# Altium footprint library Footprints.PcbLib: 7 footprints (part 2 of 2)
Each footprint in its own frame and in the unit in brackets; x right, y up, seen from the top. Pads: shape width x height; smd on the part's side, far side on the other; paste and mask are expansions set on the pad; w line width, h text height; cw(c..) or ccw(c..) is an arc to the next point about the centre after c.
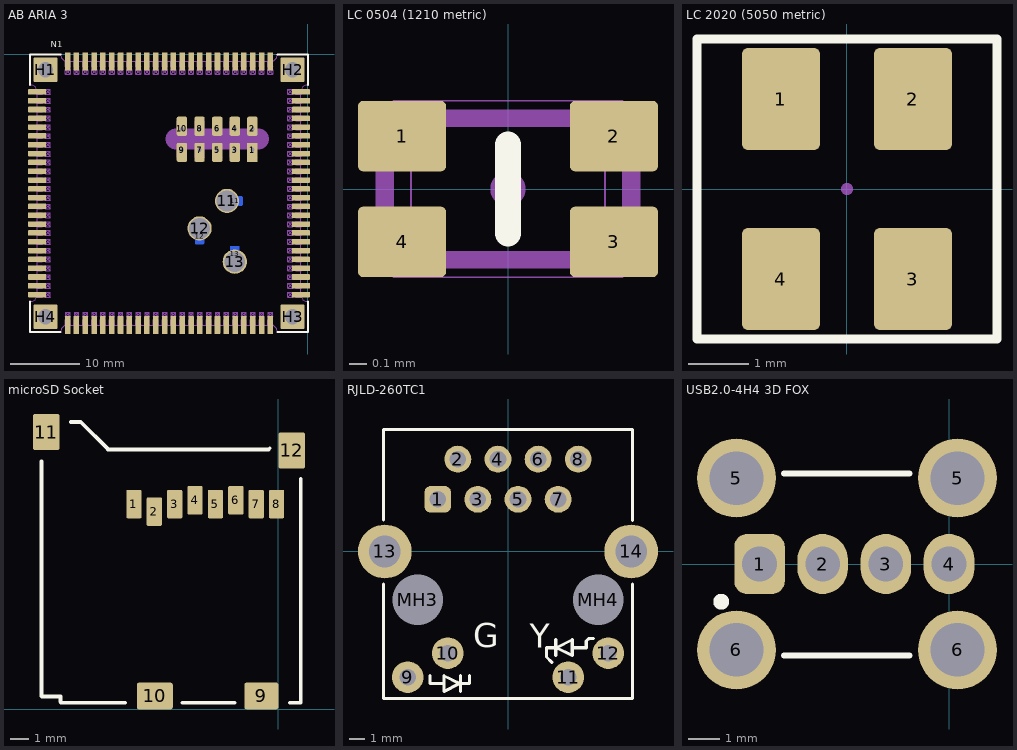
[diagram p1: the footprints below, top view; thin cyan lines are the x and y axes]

## AB ARIA 3 [mm]
height 1.7
pads (126):
  rect 1.5x2.5 hole 0.6 copper offset 0,-0.5 paste-0.1: 1(-7.98,-13.725)
  rect 1.5x2.2 smd paste+0.1: 1(-7.98,-13.83)
  rrect30% 1.5x2.5 hole 0.6 copper offset 0,0.5 paste-0.1: 2(-7.98,-10.725) 4(-10.52,-10.725) 6(-13.06,-10.725) 8(-15.6,-10.725) 10(-18.14,-10.725)
  rrect30% 1.5x2.2 smd paste+0.1: 2(-7.98,-10.62) 3(-10.52,-13.83) 4(-10.52,-10.62) 5(-13.06,-13.83) 6(-13.06,-10.62) 7(-15.6,-13.83) 8(-15.6,-10.62) 9(-18.14,-13.83) 10(-18.14,-10.62)
  rrect30% 1.5x2.5 hole 0.6 copper offset 0,-0.5 paste-0.1: 3(-10.52,-13.725) 5(-13.06,-13.725) 7(-15.6,-13.725) 9(-18.14,-13.725)
  round 3.5 hole 3 paste-1 mask+0.1: 11(-11.644,-21.115) 12(-15.6,-25.07) 13(-10.52,-29.86)
  rrect20% 2.25x1.3 smd far side: 11(-10.52,-21.115)
  rrect20% 1.3x2.25 smd far side: 12(-15.6,-26.195) 13(-10.52,-28.735)
  rrect20% 2.6x0.8 smd paste+0.05: E1(-1,-5.395) E2(-1,-6.665) E3(-1,-7.935) E4(-1,-9.205) E5(-1,-10.475) E6(-1,-11.745) E7(-1,-13.015) E8(-1,-14.285) E9(-1,-15.555) E10(-1,-16.825) E11(-1,-18.095) E12(-1,-19.365) E13(-1,-20.635) E14(-1,-21.905) E15(-1,-23.175) E16(-1,-24.445) E17(-1,-25.715) E18(-1,-26.985) E19(-1,-28.255) E20(-1,-29.525) E21(-1,-30.795) E22(-1,-32.065) E23(-1,-33.335) E24(-1,-34.605) W1(-39,-34.605) W2(-39,-33.335) W3(-39,-32.065) W4(-39,-30.795) W5(-39,-29.525) W6(-39,-28.255) W7(-39,-26.985) W8(-39,-25.715) W9(-39,-24.445) W10(-39,-23.175) W11(-39,-21.905) W12(-39,-20.635) W13(-39,-19.365) W14(-39,-18.095) W15(-39,-16.825) W16(-39,-15.555) W17(-39,-14.285) W18(-39,-13.015) W19(-39,-11.745) W20(-39,-10.475) W21(-39,-9.205) W22(-39,-7.935) W23(-39,-6.665) W24(-39,-5.395)
  rrect10% 3.5x3.5 hole 2.2 mask+0.2: H1(-37.8,-2.2) H2(-2.2,-2.2) H3(-2.2,-37.8) H4(-37.8,-37.8)
  rrect20% 0.8x2.6 smd paste+0.05: N1(-34.605,-1) N2(-33.335,-1) N3(-32.065,-1) N4(-30.795,-1) N5(-29.525,-1) N6(-28.255,-1) N7(-26.985,-1) N8(-25.715,-1) N9(-24.445,-1) N10(-23.175,-1) N11(-21.905,-1) N12(-20.635,-1) N13(-19.365,-1) N14(-18.095,-1) N15(-16.825,-1) N16(-15.555,-1) N17(-14.285,-1) N18(-13.015,-1) N19(-11.745,-1) N20(-10.475,-1) N21(-9.205,-1) N22(-7.935,-1) N23(-6.665,-1) N24(-5.395,-1) S1(-5.395,-39) S2(-6.665,-39) S3(-7.935,-39) S4(-9.205,-39) S5(-10.475,-39) S6(-11.745,-39) S7(-13.015,-39) S8(-14.285,-39) S9(-15.555,-39) S10(-16.825,-39) S11(-18.095,-39) S12(-19.365,-39) S13(-20.635,-39) S14(-21.905,-39) S15(-23.175,-39) S16(-24.445,-39) S17(-25.715,-39) S18(-26.985,-39) S19(-28.255,-39) S20(-29.525,-39) S21(-30.795,-39) S22(-32.065,-39) S23(-33.335,-39) S24(-34.605,-39)
Top Overlay:
  lines w0.3: -40,-35.605 -40,-40 ; -40,-4.395 -40,0 -35.605,0 ; -35.605,-40 -40,-40 ; -4.395,-40 0,-40 0,-35.605 ; -4.395,0 0,0 ; 0,-4.395 0,0 ; -40,-40 -40,-40 ; -35.605,0 -35.605,0 ; 0,0 0,0
  text "N1" at -37.034,0.701 h1.52
Top Paste:
  lines w0.9: -40.752,-7.933 -40.452,-7.933 ; -40.75,-33.335 -40.45,-33.335 ; -40.75,-32.065 -40.45,-32.065 ; -40.75,-30.795 -40.45,-30.795 ; -40.75,-29.525 -40.45,-29.525 ; -40.75,-28.255 -40.45,-28.255 ; -40.75,-26.985 -40.45,-26.985 ; -40.75,-25.715 -40.45,-25.715 ; -40.75,-24.445 -40.45,-24.445 ; -40.75,-23.175 -40.45,-23.175 ; -40.75,-21.905 -40.45,-21.905 ; -40.75,-20.635 -40.45,-20.635 ; -40.75,-19.365 -40.45,-19.365 ; -40.75,-18.095 -40.45,-18.095 ; -40.75,-16.825 -40.45,-16.825 ; -40.75,-15.555 -40.45,-15.555 ; -40.75,-13.015 -40.45,-13.015 ; -40.75,-11.745 -40.45,-11.745 ; -40.75,-10.475 -40.45,-10.475 ; -40.75,-9.205 -40.45,-9.205 ; -40.75,-6.665 -40.45,-6.665 ; -40.75,-5.395 -40.45,-5.395 ; -40.749,-34.604 -40.449,-34.604 ; -34.605,-40.75 -34.605,-40.45 ; -34.605,0.45 -34.605,0.75 ; -33.335,-40.75 -33.335,-40.45 ; -33.335,0.45 -33.335,0.75 ; -32.065,-40.75 -32.065,-40.45 ; -32.065,0.45 -32.065,0.75 ; -30.795,-40.75 -30.795,-40.45 ; -30.795,0.45 -30.795,0.75 ; -29.525,-40.75 -29.525,-40.45 ; -29.525,0.45 -29.525,0.75 ; -28.255,-40.75 -28.255,-40.45 ; -28.255,0.45 -28.255,0.75 ; -26.985,-40.75 -26.985,-40.45 ; -26.985,0.45 -26.985,0.75 ; -25.715,-40.75 -25.715,-40.45 ; -25.715,0.45 -25.715,0.75 ; -24.445,-40.75 -24.445,-40.45 ; -24.445,0.45 -24.445,0.75 ; -23.175,-40.75 -23.175,-40.45 ; -23.175,0.45 -23.175,0.75 ; -21.905,-40.75 -21.905,-40.45 ; -21.905,0.45 -21.905,0.75 ; -20.635,-40.75 -20.635,-40.45 ; -20.635,0.45 -20.635,0.75 ; -19.365,-40.75 -19.365,-40.45 ; -19.365,0.45 -19.365,0.75 ; -18.095,-40.75 -18.095,-40.45 ; -18.095,0.45 -18.095,0.75 ; -16.825,-40.75 -16.825,-40.45 ; -16.825,0.45 -16.825,0.75 ; -15.555,-40.75 -15.555,-40.45 ; -15.555,0.45 -15.555,0.75 ; -14.285,-40.75 -14.285,-40.45 ; -14.285,0.45 -14.285,0.75 ; -13.015,-40.75 -13.015,-40.45 ; -13.015,0.45 -13.015,0.75 ; -11.745,-40.75 -11.745,-40.45 ; -11.745,0.45 -11.745,0.75 ; -10.475,-40.75 -10.475,-40.45 ; -10.475,0.45 -10.475,0.75 ; -9.205,-40.75 -9.205,-40.45 ; -9.205,0.45 -9.205,0.75 ; -7.935,-40.75 -7.935,-40.45 ; -7.935,0.45 -7.935,0.75 ; -6.665,-40.75 -6.665,-40.45 ; -6.665,0.45 -6.665,0.75 ; -5.395,-40.75 -5.395,-40.45 ; -5.395,0.45 -5.395,0.75 ; 0.45,-34.605 0.75,-34.605 ; 0.45,-33.335 0.75,-33.335 ; 0.45,-32.065 0.75,-32.065 ; 0.45,-30.795 0.75,-30.795 ; 0.45,-29.525 0.75,-29.525 ; 0.45,-28.255 0.75,-28.255 ; 0.45,-26.985 0.75,-26.985 ; 0.45,-25.715 0.75,-25.715 ; 0.45,-24.445 0.75,-24.445 ; 0.45,-23.175 0.75,-23.175 ; 0.45,-21.905 0.75,-21.905 ; 0.45,-20.635 0.75,-20.635 ; 0.45,-19.365 0.75,-19.365 ; 0.45,-18.095 0.75,-18.095 ; 0.45,-16.825 0.75,-16.825 ; 0.45,-15.555 0.75,-15.555 ; 0.45,-14.285 0.75,-14.285 ; 0.45,-13.015 0.75,-13.015 ; 0.45,-11.745 0.75,-11.745 ; 0.45,-10.475 0.75,-10.475 ; 0.45,-9.205 0.75,-9.205 ; 0.45,-7.935 0.75,-7.935 ; 0.45,-6.665 0.75,-6.665 ; 0.45,-5.395 0.75,-5.395 ; -40.75,-14.285 -40.45,-14.285 -40.75,-14.285
Mechanical 1:
  lines w0.1: -5.395,-39 cw(c-5.395,-40) -4.395,-40 0,-40 0,-35.605 cw(c0,-34.605) -1,-34.605 -1,-5.395 cw(c0,-5.395) 0,-4.395 0,0 -4.395,0 cw(c-5.395,0) -5.395,-1 -34.605,-1 cw(c-34.605,0) -35.605,0 -40,0 -40,-4.395 cw(c-40,-5.395) -39,-5.395 -39,-34.605 cw(c-40,-34.605) -40,-35.605 -40,-40 -35.605,-40 cw(c-34.605,-40) -34.605,-39 -5.345,-39
Mechanical 6:
  lines w3: -19,-12.2 -7.12,-12.2
Mechanical 15:
  drawing of 1308 lines, arcs and shapes, not listed
3D body: height 0.02, standoff -0.03, extent -11.214,-29.433 -9.82,-28.036
3D body: height 0.02, standoff -0.03, extent -16.294,-26.893 -14.9,-25.496
3D body: height 0.1, standoff 0.01, extent -18.79,-14.83 -17.49,-12.83
3D body: height 0.1, standoff 0.01, extent -16.25,-14.83 -14.95,-12.83
3D body: height 0.1, standoff 0.01, extent -13.71,-14.83 -12.41,-12.83
3D body: height 0.1, standoff 0.01, extent -11.17,-14.83 -9.87,-12.83
3D body: height 0.1, standoff 0.01, extent -8.63,-14.83 -7.33,-12.83
3D body: height 0.1, standoff 0.01, extent -18.79,-11.62 -17.49,-9.62
3D body: height 0.1, standoff 0.01, extent -16.25,-11.62 -14.95,-9.62
3D body: height 0.1, standoff 0.01, extent -13.71,-11.62 -12.41,-9.62
3D body: height 0.1, standoff 0.01, extent -11.17,-11.62 -9.87,-9.62
3D body: height 0.1, standoff 0.01, extent -8.63,-11.62 -7.33,-9.62
3D body: height 1.51, standoff 0.01, extent -20.64,-6.3 -19.28,-4.73
3D body: height 1.51, standoff 0.01, extent -21.599,-4.001 -18.4,-2.4
3D body: height 1.51, standoff 1.4, extent -2.18,-5.745 -0.95,-5.045
3D body: height 0.1, standoff 0.01, extent -2.88,-5.745 -2.18,-5.045
3D body: height 1.4, standoff 0.01, extent -1.77,-5.745 -0.95,-5.045
3D body: height 1.4, standoff 0.01, extent -1.77,-7.015 -0.95,-6.315
3D body: height 0.1, standoff 0.01, extent -2.88,-7.015 -2.18,-6.315
3D body: height 1.51, standoff 1.4, extent -1.77,-7.015 -0.95,-6.315
3D body: height 1.4, standoff 0.01, extent -1.77,-8.285 -0.95,-7.585
3D body: height 0.1, standoff 0.01, extent -2.88,-8.285 -2.18,-7.585
3D body: height 1.51, standoff 1.4, extent -1.77,-8.285 -0.95,-7.585
3D body: height 1.4, standoff 0.01, extent -1.77,-9.555 -0.95,-8.855
3D body: height 0.1, standoff 0.01, extent -2.88,-9.555 -2.18,-8.855
3D body: height 1.51, standoff 1.4, extent -1.77,-9.555 -0.95,-8.855
3D body: height 1.4, standoff 0.01, extent -1.77,-10.825 -0.95,-10.125
3D body: height 0.1, standoff 0.01, extent -2.88,-10.825 -2.18,-10.125
3D body: height 1.51, standoff 1.4, extent -1.77,-10.825 -0.95,-10.125
3D body: height 1.4, standoff 0.01, extent -1.77,-12.095 -0.95,-11.395
3D body: height 0.1, standoff 0.01, extent -2.88,-12.095 -2.18,-11.395
3D body: height 1.51, standoff 1.4, extent -1.77,-12.095 -0.95,-11.395
3D body: height 1.4, standoff 0.01, extent -1.77,-13.365 -0.95,-12.665
3D body: height 0.1, standoff 0.01, extent -2.88,-13.365 -2.18,-12.665
3D body: height 1.51, standoff 1.4, extent -1.77,-13.365 -0.95,-12.665
3D body: height 1.4, standoff 0.01, extent -1.77,-14.635 -0.95,-13.935
3D body: height 0.1, standoff 0.01, extent -2.88,-14.635 -2.18,-13.935
3D body: height 1.51, standoff 1.4, extent -1.77,-14.635 -0.95,-13.935
3D body: height 1.4, standoff 0.01, extent -1.77,-15.905 -0.95,-15.205
3D body: height 0.1, standoff 0.01, extent -2.88,-15.905 -2.18,-15.205
3D body: height 1.51, standoff 1.4, extent -1.77,-15.905 -0.95,-15.205
3D body: height 1.4, standoff 0.01, extent -1.77,-17.175 -0.95,-16.475
3D body: height 0.1, standoff 0.01, extent -2.88,-17.175 -2.18,-16.475
3D body: height 1.51, standoff 1.4, extent -1.77,-17.175 -0.95,-16.475
3D body: height 1.4, standoff 0.01, extent -1.77,-18.445 -0.95,-17.745
3D body: height 0.1, standoff 0.01, extent -2.88,-18.445 -2.18,-17.745
3D body: height 1.51, standoff 1.4, extent -1.77,-18.445 -0.95,-17.745
3D body: height 1.4, standoff 0.01, extent -1.77,-19.715 -0.95,-19.015
3D body: height 0.1, standoff 0.01, extent -2.88,-19.715 -2.18,-19.015
3D body: height 1.51, standoff 1.4, extent -1.77,-19.715 -0.95,-19.015
3D body: height 1.4, standoff 0.01, extent -1.77,-20.985 -0.95,-20.285
3D body: height 0.1, standoff 0.01, extent -2.88,-20.985 -2.18,-20.285
3D body: height 1.51, standoff 1.4, extent -1.77,-20.985 -0.95,-20.285
3D body: height 1.4, standoff 0.01, extent -1.77,-22.255 -0.95,-21.555
3D body: height 0.1, standoff 0.01, extent -2.88,-22.255 -2.18,-21.555
3D body: height 1.51, standoff 1.4, extent -1.77,-22.255 -0.95,-21.555
3D body: height 1.4, standoff 0.01, extent -1.77,-23.525 -0.95,-22.825
3D body: height 0.1, standoff 0.01, extent -2.88,-23.525 -2.18,-22.825
3D body: height 1.51, standoff 1.4, extent -1.77,-23.525 -0.95,-22.825
3D body: height 1.4, standoff 0.01, extent -1.77,-24.795 -0.95,-24.095
3D body: height 0.1, standoff 0.01, extent -2.88,-24.795 -2.18,-24.095
3D body: height 1.51, standoff 1.4, extent -1.77,-24.795 -0.95,-24.095
3D body: height 1.4, standoff 0.01, extent -1.77,-26.065 -0.95,-25.365
3D body: height 0.1, standoff 0.01, extent -2.88,-26.065 -2.18,-25.365
3D body: height 1.51, standoff 1.4, extent -1.77,-26.065 -0.95,-25.365
3D body: height 1.4, standoff 0.01, extent -1.77,-27.335 -0.95,-26.635
3D body: height 0.1, standoff 0.01, extent -2.88,-27.335 -2.18,-26.635
3D body: height 1.51, standoff 1.4, extent -1.77,-27.335 -0.95,-26.635
3D body: height 1.4, standoff 0.01, extent -1.77,-28.605 -0.95,-27.905
3D body: height 0.1, standoff 0.01, extent -2.88,-28.605 -2.18,-27.905
3D body: height 1.51, standoff 1.4, extent -1.77,-28.605 -0.95,-27.905
3D body: height 1.4, standoff 0.01, extent -1.77,-29.875 -0.95,-29.175
3D body: height 0.1, standoff 0.01, extent -2.88,-29.875 -2.18,-29.175
3D body: height 1.51, standoff 1.4, extent -1.77,-29.875 -0.95,-29.175
3D body: height 1.4, standoff 0.01, extent -1.77,-31.145 -0.95,-30.445
3D body: height 0.1, standoff 0.01, extent -2.88,-31.145 -2.18,-30.445
3D body: height 1.51, standoff 1.4, extent -1.77,-31.145 -0.95,-30.445
3D body: height 1.4, standoff 0.01, extent -1.77,-32.415 -0.95,-31.715
3D body: height 0.1, standoff 0.01, extent -2.88,-32.415 -2.18,-31.715
3D body: height 1.51, standoff 1.4, extent -1.77,-32.415 -0.95,-31.715
3D body: height 1.4, standoff 0.01, extent -1.77,-33.685 -0.95,-32.985
3D body: height 0.1, standoff 0.01, extent -2.88,-33.685 -2.18,-32.985
3D body: height 1.51, standoff 1.4, extent -1.77,-33.685 -0.95,-32.985
3D body: height 1.4, standoff 0.01, extent -1.77,-34.955 -0.95,-34.255
3D body: height 0.1, standoff 0.01, extent -2.88,-34.955 -2.18,-34.255
3D body: height 1.51, standoff 1.4, extent -1.77,-34.955 -0.95,-34.255
3D body: height 1.4, standoff 0.01, extent -5.745,-39.05 -5.045,-38.23
3D body: height 0.1, standoff 0.01, extent -5.745,-37.82 -5.045,-37.12
3D body: height 1.51, standoff 1.4, extent -5.745,-39.05 -5.045,-37.82
3D body: height 1.4, standoff 0.01, extent -7.015,-39.05 -6.315,-38.23
3D body: height 0.1, standoff 0.01, extent -7.015,-37.82 -6.315,-37.12
3D body: height 1.51, standoff 1.4, extent -7.015,-39.05 -6.315,-38.23
3D body: height 1.4, standoff 0.01, extent -8.285,-39.05 -7.585,-38.23
3D body: height 0.1, standoff 0.01, extent -8.285,-37.82 -7.585,-37.12
3D body: height 1.51, standoff 1.4, extent -8.285,-39.05 -7.585,-38.23
3D body: height 1.4, standoff 0.01, extent -9.555,-39.05 -8.855,-38.23
3D body: height 0.1, standoff 0.01, extent -9.555,-37.82 -8.855,-37.12
3D body: height 1.51, standoff 1.4, extent -9.555,-39.05 -8.855,-38.23
3D body: height 1.4, standoff 0.01, extent -10.825,-39.05 -10.125,-38.23
3D body: height 0.1, standoff 0.01, extent -10.825,-37.82 -10.125,-37.12
3D body: height 1.51, standoff 1.4, extent -10.825,-39.05 -10.125,-38.23
3D body: height 1.4, standoff 0.01, extent -12.095,-39.05 -11.395,-38.23
3D body: height 0.1, standoff 0.01, extent -12.095,-37.82 -11.395,-37.12
3D body: height 1.51, standoff 1.4, extent -12.095,-39.05 -11.395,-38.23
3D body: height 1.4, standoff 0.01, extent -13.365,-39.05 -12.665,-38.23
3D body: height 0.1, standoff 0.01, extent -13.365,-37.82 -12.665,-37.12
3D body: height 1.51, standoff 1.4, extent -13.365,-39.05 -12.665,-38.23
3D body: height 1.4, standoff 0.01, extent -14.635,-39.05 -13.935,-38.23
3D body: height 0.1, standoff 0.01, extent -14.635,-37.82 -13.935,-37.12
3D body: height 1.51, standoff 1.4, extent -14.635,-39.05 -13.935,-38.23
3D body: height 1.4, standoff 0.01, extent -15.905,-39.05 -15.205,-38.23
3D body: height 0.1, standoff 0.01, extent -15.905,-37.82 -15.205,-37.12
3D body: height 1.51, standoff 1.4, extent -15.905,-39.05 -15.205,-38.23
3D body: height 1.4, standoff 0.01, extent -17.175,-39.05 -16.475,-38.23
3D body: height 0.1, standoff 0.01, extent -17.175,-37.82 -16.475,-37.12
3D body: height 1.51, standoff 1.4, extent -17.175,-39.05 -16.475,-38.23
3D body: height 1.4, standoff 0.01, extent -18.445,-39.05 -17.745,-38.23
3D body: height 0.1, standoff 0.01, extent -18.445,-37.82 -17.745,-37.12
3D body: height 1.51, standoff 1.4, extent -18.445,-39.05 -17.745,-38.23
3D body: height 1.4, standoff 0.01, extent -19.715,-39.05 -19.015,-38.23
3D body: height 0.1, standoff 0.01, extent -19.715,-37.82 -19.015,-37.12
3D body: height 1.51, standoff 1.4, extent -19.715,-39.05 -19.015,-38.23
3D body: height 1.4, standoff 0.01, extent -20.985,-39.05 -20.285,-38.23
3D body: height 0.1, standoff 0.01, extent -20.985,-37.82 -20.285,-37.12
3D body: height 1.51, standoff 1.4, extent -20.985,-39.05 -20.285,-38.23
3D body: height 1.4, standoff 0.01, extent -22.255,-39.05 -21.555,-38.23
3D body: height 0.1, standoff 0.01, extent -22.255,-37.82 -21.555,-37.12
3D body: height 1.51, standoff 1.4, extent -22.255,-39.05 -21.555,-38.23
3D body: height 1.4, standoff 0.01, extent -23.525,-39.05 -22.825,-38.23
3D body: height 0.1, standoff 0.01, extent -23.525,-37.82 -22.825,-37.12
3D body: height 1.51, standoff 1.4, extent -23.525,-39.05 -22.825,-38.23
3D body: height 1.4, standoff 0.01, extent -24.795,-39.05 -24.095,-38.23
3D body: height 0.1, standoff 0.01, extent -24.795,-37.82 -24.095,-37.12
3D body: height 1.51, standoff 1.4, extent -24.795,-39.05 -24.095,-38.23
3D body: height 1.4, standoff 0.01, extent -26.065,-39.05 -25.365,-38.23
3D body: height 0.1, standoff 0.01, extent -26.065,-37.82 -25.365,-37.12
3D body: height 1.51, standoff 1.4, extent -26.065,-39.05 -25.365,-38.23
3D body: height 1.4, standoff 0.01, extent -27.335,-39.05 -26.635,-38.23
3D body: height 0.1, standoff 0.01, extent -27.335,-37.82 -26.635,-37.12
3D body: height 1.51, standoff 1.4, extent -27.335,-39.05 -26.635,-38.23
3D body: height 1.4, standoff 0.01, extent -28.605,-39.05 -27.905,-38.23
3D body: height 0.1, standoff 0.01, extent -28.605,-37.82 -27.905,-37.12
3D body: height 1.51, standoff 1.4, extent -28.605,-39.05 -27.905,-38.23
3D body: height 1.4, standoff 0.01, extent -29.875,-39.05 -29.175,-38.23
3D body: height 0.1, standoff 0.01, extent -29.875,-37.82 -29.175,-37.12
3D body: height 1.51, standoff 1.4, extent -29.875,-39.05 -29.175,-38.23
3D body: height 1.4, standoff 0.01, extent -31.145,-39.05 -30.445,-38.23
3D body: height 0.1, standoff 0.01, extent -31.145,-37.82 -30.445,-37.12
3D body: height 1.51, standoff 1.4, extent -31.145,-39.05 -30.445,-38.23
3D body: height 1.4, standoff 0.01, extent -32.415,-39.05 -31.715,-38.23
3D body: height 0.1, standoff 0.01, extent -32.415,-37.82 -31.715,-37.12
3D body: height 1.51, standoff 1.4, extent -32.415,-39.05 -31.715,-38.23
3D body: height 1.4, standoff 0.01, extent -33.685,-39.05 -32.985,-38.23
3D body: height 0.1, standoff 0.01, extent -33.685,-37.82 -32.985,-37.12
3D body: height 1.51, standoff 1.4, extent -33.685,-39.05 -32.985,-38.23
3D body: height 1.4, standoff 0.01, extent -34.955,-39.05 -34.255,-38.23
3D body: height 0.1, standoff 0.01, extent -34.955,-37.82 -34.255,-37.12
3D body: height 1.51, standoff 1.4, extent -34.955,-39.05 -34.255,-38.23
3D body: height 1.4, standoff 0.01, extent -39.05,-34.955 -38.23,-34.255
3D body: height 0.1, standoff 0.01, extent -37.82,-34.955 -37.12,-34.255
3D body: height 1.51, standoff 1.4, extent -39.05,-34.955 -37.82,-34.255
3D body: height 1.4, standoff 0.01, extent -39.05,-33.685 -38.23,-32.985
3D body: height 0.1, standoff 0.01, extent -37.82,-33.685 -37.12,-32.985
3D body: height 1.51, standoff 1.4, extent -39.05,-33.685 -38.23,-32.985
3D body: height 1.4, standoff 0.01, extent -39.05,-32.415 -38.23,-31.715
3D body: height 0.1, standoff 0.01, extent -37.82,-32.415 -37.12,-31.715
3D body: height 1.51, standoff 1.4, extent -39.05,-32.415 -38.23,-31.715
3D body: height 1.4, standoff 0.01, extent -39.05,-31.145 -38.23,-30.445
3D body: height 0.1, standoff 0.01, extent -37.82,-31.145 -37.12,-30.445
3D body: height 1.51, standoff 1.4, extent -39.05,-31.145 -38.23,-30.445
3D body: height 1.4, standoff 0.01, extent -39.05,-29.875 -38.23,-29.175
3D body: height 0.1, standoff 0.01, extent -37.82,-29.875 -37.12,-29.175
3D body: height 1.51, standoff 1.4, extent -39.05,-29.875 -38.23,-29.175
3D body: height 1.4, standoff 0.01, extent -39.05,-28.605 -38.23,-27.905
3D body: height 0.1, standoff 0.01, extent -37.82,-28.605 -37.12,-27.905
3D body: height 1.51, standoff 1.4, extent -39.05,-28.605 -38.23,-27.905
3D body: height 1.4, standoff 0.01, extent -39.05,-27.335 -38.23,-26.635
3D body: height 0.1, standoff 0.01, extent -37.82,-27.335 -37.12,-26.635
3D body: height 1.51, standoff 1.4, extent -39.05,-27.335 -38.23,-26.635
3D body: height 1.4, standoff 0.01, extent -39.05,-26.065 -38.23,-25.365
3D body: height 0.1, standoff 0.01, extent -37.82,-26.065 -37.12,-25.365
3D body: height 1.51, standoff 1.4, extent -39.05,-26.065 -38.23,-25.365
3D body: height 1.4, standoff 0.01, extent -39.05,-24.795 -38.23,-24.095
3D body: height 0.1, standoff 0.01, extent -37.82,-24.795 -37.12,-24.095
3D body: height 1.51, standoff 1.4, extent -39.05,-24.795 -38.23,-24.095
3D body: height 1.4, standoff 0.01, extent -39.05,-23.525 -38.23,-22.825
3D body: height 0.1, standoff 0.01, extent -37.82,-23.525 -37.12,-22.825
3D body: height 1.51, standoff 1.4, extent -39.05,-23.525 -38.23,-22.825
3D body: height 1.4, standoff 0.01, extent -39.05,-22.255 -38.23,-21.555
3D body: height 0.1, standoff 0.01, extent -37.82,-22.255 -37.12,-21.555
3D body: height 1.51, standoff 1.4, extent -39.05,-22.255 -38.23,-21.555
3D body: height 1.4, standoff 0.01, extent -39.05,-20.985 -38.23,-20.285
3D body: height 0.1, standoff 0.01, extent -37.82,-20.985 -37.12,-20.285
3D body: height 1.51, standoff 1.4, extent -39.05,-20.985 -38.23,-20.285
3D body: height 1.4, standoff 0.01, extent -39.05,-19.715 -38.23,-19.015
3D body: height 0.1, standoff 0.01, extent -37.82,-19.715 -37.12,-19.015
3D body: height 1.51, standoff 1.4, extent -39.05,-19.715 -38.23,-19.015
3D body: height 1.4, standoff 0.01, extent -39.05,-18.445 -38.23,-17.745
3D body: height 0.1, standoff 0.01, extent -37.82,-18.445 -37.12,-17.745
3D body: height 1.51, standoff 1.4, extent -39.05,-18.445 -38.23,-17.745
3D body: height 1.4, standoff 0.01, extent -39.05,-17.175 -38.23,-16.475
3D body: height 0.1, standoff 0.01, extent -37.82,-17.175 -37.12,-16.475
3D body: height 1.51, standoff 1.4, extent -39.05,-17.175 -38.23,-16.475
3D body: height 1.4, standoff 0.01, extent -39.05,-15.905 -38.23,-15.205
3D body: height 0.1, standoff 0.01, extent -37.82,-15.905 -37.12,-15.205
3D body: height 1.51, standoff 1.4, extent -39.05,-15.905 -38.23,-15.205
3D body: height 1.4, standoff 0.01, extent -39.05,-14.635 -38.23,-13.935
3D body: height 0.1, standoff 0.01, extent -37.82,-14.635 -37.12,-13.935
3D body: height 1.51, standoff 1.4, extent -39.05,-14.635 -38.23,-13.935
3D body: height 1.4, standoff 0.01, extent -39.05,-13.365 -38.23,-12.665
3D body: height 0.1, standoff 0.01, extent -37.82,-13.365 -37.12,-12.665
3D body: height 1.51, standoff 1.4, extent -39.05,-13.365 -38.23,-12.665
3D body: height 1.4, standoff 0.01, extent -39.05,-12.095 -38.23,-11.395
3D body: height 0.1, standoff 0.01, extent -37.82,-12.095 -37.12,-11.395
3D body: height 1.51, standoff 1.4, extent -39.05,-12.095 -38.23,-11.395
3D body: height 1.4, standoff 0.01, extent -39.05,-10.825 -38.23,-10.125
3D body: height 0.1, standoff 0.01, extent -37.82,-10.825 -37.12,-10.125
3D body: height 1.51, standoff 1.4, extent -39.05,-10.825 -38.23,-10.125
3D body: height 1.4, standoff 0.01, extent -39.05,-9.555 -38.23,-8.855
3D body: height 0.1, standoff 0.01, extent -37.82,-9.555 -37.12,-8.855
3D body: height 1.51, standoff 1.4, extent -39.05,-9.555 -38.23,-8.855
3D body: height 1.4, standoff 0.01, extent -39.05,-8.285 -38.23,-7.585
3D body: height 0.1, standoff 0.01, extent -37.82,-8.285 -37.12,-7.585
3D body: height 1.51, standoff 1.4, extent -39.05,-8.285 -38.23,-7.585
3D body: height 1.4, standoff 0.01, extent -39.05,-7.015 -38.23,-6.315
3D body: height 0.1, standoff 0.01, extent -37.82,-7.015 -37.12,-6.315
3D body: height 1.51, standoff 1.4, extent -39.05,-7.015 -38.23,-6.315
3D body: height 1.4, standoff 0.01, extent -39.05,-5.745 -38.23,-5.045
3D body: height 0.1, standoff 0.01, extent -37.82,-5.745 -37.12,-5.045
3D body: height 1.51, standoff 1.4, extent -39.05,-5.745 -38.23,-5.045
3D body: height 1.4, standoff 0.01, extent -34.955,-1.77 -34.255,-0.95
3D body: height 0.1, standoff 0.01, extent -34.955,-2.88 -34.255,-2.18
3D body: height 1.51, standoff 1.4, extent -34.955,-2.18 -34.255,-0.95
3D body: height 1.4, standoff 0.01, extent -33.685,-1.77 -32.985,-0.95
3D body: height 0.1, standoff 0.01, extent -33.685,-2.88 -32.985,-2.18
3D body: height 1.51, standoff 1.4, extent -33.685,-1.77 -32.985,-0.95
3D body: height 1.4, standoff 0.01, extent -32.415,-1.77 -31.715,-0.95
3D body: height 0.1, standoff 0.01, extent -32.415,-2.88 -31.715,-2.18
3D body: height 1.51, standoff 1.4, extent -32.415,-1.77 -31.715,-0.95
3D body: height 1.4, standoff 0.01, extent -31.145,-1.77 -30.445,-0.95
3D body: height 0.1, standoff 0.01, extent -31.145,-2.88 -30.445,-2.18
3D body: height 1.51, standoff 1.4, extent -31.145,-1.77 -30.445,-0.95
3D body: height 1.4, standoff 0.01, extent -29.875,-1.77 -29.175,-0.95
3D body: height 0.1, standoff 0.01, extent -29.875,-2.88 -29.175,-2.18
3D body: height 1.51, standoff 1.4, extent -29.875,-1.77 -29.175,-0.95
3D body: height 1.4, standoff 0.01, extent -28.605,-1.77 -27.905,-0.95
3D body: height 0.1, standoff 0.01, extent -28.605,-2.88 -27.905,-2.18
3D body: height 1.51, standoff 1.4, extent -28.605,-1.77 -27.905,-0.95
3D body: height 1.4, standoff 0.01, extent -27.335,-1.77 -26.635,-0.95
3D body: height 0.1, standoff 0.01, extent -27.335,-2.88 -26.635,-2.18
3D body: height 1.51, standoff 1.4, extent -27.335,-1.77 -26.635,-0.95
3D body: height 1.4, standoff 0.01, extent -26.065,-1.77 -25.365,-0.95
3D body: height 0.1, standoff 0.01, extent -26.065,-2.88 -25.365,-2.18
3D body: height 1.51, standoff 1.4, extent -26.065,-1.77 -25.365,-0.95
3D body: height 1.51, standoff 1.4, extent -24.795,-1.77 -24.095,-0.95
3D body: height 0.1, standoff 0.01, extent -24.795,-2.88 -24.095,-2.18
3D body: height 1.4, standoff 0.01, extent -24.795,-1.77 -24.095,-0.95
3D body: height 1.51, standoff 1.4, extent -23.525,-1.77 -22.825,-0.95
3D body: height 0.1, standoff 0.01, extent -23.525,-2.88 -22.825,-2.18
3D body: height 1.4, standoff 0.01, extent -23.525,-1.77 -22.825,-0.95
3D body: height 1.51, standoff 1.4, extent -22.255,-1.77 -21.555,-0.95
3D body: height 0.1, standoff 0.01, extent -22.255,-2.88 -21.555,-2.18
3D body: height 1.4, standoff 0.01, extent -22.255,-1.77 -21.555,-0.95
3D body: height 1.51, standoff 1.4, extent -20.985,-1.77 -20.285,-0.95
3D body: height 0.1, standoff 0.01, extent -20.985,-2.88 -20.285,-2.18
3D body: height 1.4, standoff 0.01, extent -20.985,-1.77 -20.285,-0.95
3D body: height 1.51, standoff 1.4, extent -19.715,-1.77 -19.015,-0.95
3D body: height 0.1, standoff 0.01, extent -19.715,-2.88 -19.015,-2.18
3D body: height 1.4, standoff 0.01, extent -19.715,-1.77 -19.015,-0.95
3D body: height 1.51, standoff 1.4, extent -18.445,-1.77 -17.745,-0.95
3D body: height 0.1, standoff 0.01, extent -18.445,-2.88 -17.745,-2.18
3D body: height 1.4, standoff 0.01, extent -18.445,-1.77 -17.745,-0.95
3D body: height 1.51, standoff 1.4, extent -17.175,-1.77 -16.475,-0.95
3D body: height 0.1, standoff 0.01, extent -17.175,-2.88 -16.475,-2.18
3D body: height 1.4, standoff 0.01, extent -17.175,-1.77 -16.475,-0.95
3D body: height 1.51, standoff 1.4, extent -15.905,-1.77 -15.205,-0.95
3D body: height 0.1, standoff 0.01, extent -15.905,-2.88 -15.205,-2.18
3D body: height 1.4, standoff 0.01, extent -15.905,-1.77 -15.205,-0.95
3D body: height 1.51, standoff 1.4, extent -14.635,-1.77 -13.935,-0.95
3D body: height 0.1, standoff 0.01, extent -14.635,-2.88 -13.935,-2.18
3D body: height 1.4, standoff 0.01, extent -14.635,-1.77 -13.935,-0.95
3D body: height 1.51, standoff 1.4, extent -13.365,-1.77 -12.665,-0.95
3D body: height 0.1, standoff 0.01, extent -13.365,-2.88 -12.665,-2.18
3D body: height 1.4, standoff 0.01, extent -13.365,-1.77 -12.665,-0.95
3D body: height 1.51, standoff 1.4, extent -12.095,-1.77 -11.395,-0.95
3D body: height 0.1, standoff 0.01, extent -12.095,-2.88 -11.395,-2.18
3D body: height 1.4, standoff 0.01, extent -12.095,-1.77 -11.395,-0.95
3D body: height 1.51, standoff 1.4, extent -5.745,-1.77 -5.045,-0.95
3D body: height 0.1, standoff 0.01, extent -5.745,-2.88 -5.045,-2.18
3D body: height 1.4, standoff 0.01, extent -5.745,-1.77 -5.045,-0.95
3D body: height 1.51, standoff 1.4, extent -7.015,-1.77 -6.315,-0.95
3D body: height 0.1, standoff 0.01, extent -7.015,-2.88 -6.315,-2.18
3D body: height 1.4, standoff 0.01, extent -7.015,-1.77 -6.315,-0.95
3D body: height 1.51, standoff 1.4, extent -8.285,-1.77 -7.585,-0.95
3D body: height 0.1, standoff 0.01, extent -8.285,-2.88 -7.585,-2.18
3D body: height 1.4, standoff 0.01, extent -8.285,-1.77 -7.585,-0.95
3D body: height 1.51, standoff 1.4, extent -9.555,-1.77 -8.855,-0.95
3D body: height 0.1, standoff 0.01, extent -9.555,-2.88 -8.855,-2.18
3D body: height 1.4, standoff 0.01, extent -9.555,-1.77 -8.855,-0.95
3D body: height 1.51, standoff 1.4, extent -10.825,-1.77 -10.125,-0.95
3D body: height 0.1, standoff 0.01, extent -10.825,-2.88 -10.125,-2.18
3D body: height 1.4, standoff 0.01, extent -10.825,-1.77 -10.125,-0.95
3D body "Aria.step": height 2.75, standoff 0.01, extent -40.055,-40.055 0.054,0.054

## LC 0504 (1210 metric) [mm]
height 0.8
pads (4):
  rrect15% 0.5x0.4 smd paste-0.015 mask+0.05: 1(-0.6,0.3) 2(0.6,0.3) 3(0.6,-0.3) 4(-0.6,-0.3)
Top Overlay:
  lines w0.15: 0,-0.25 0,0.25
Mechanical 13:
  lines w0.01: -0.65,-0.4 -0.55,-0.4 ; -0.65,-0.11 -0.55,-0.11 ; -0.65,0.11 -0.55,0.11 ; -0.65,0.4 -0.55,0.4 ; -0.55,-0.5 -0.55,0.5 ; 0.55,-0.5 0.55,0.5 ; 0.55,-0.4 0.65,-0.4 ; 0.55,-0.11 0.65,-0.11 ; 0.55,0.11 0.65,0.11 ; 0.55,0.4 0.65,0.4 ; -0.65,-0.5 -0.65,0.5 0.65,0.5 0.65,-0.5 -0.65,-0.5
Mechanical 15:
  circle w0.1: c0,0 r0.05
  lines w0.1: -0.7,-0.4 0.7,-0.4 0.7,0.4 -0.7,0.4 -0.7,-0.4
3D body: height 0.8, standoff 0.02, extent -0.64,-0.5 0.64,0.5
3D body: height 0.81, standoff 0.01, extent -0.65,-0.41 -0.55,-0.11
3D body: height 0.81, standoff 0.01, extent 0.55,0.11 0.65,0.4
3D body: height 0.81, standoff 0.01, extent 0.55,-0.4 0.65,-0.11
3D body: height 0.81, standoff 0.01, extent -0.65,0.11 -0.55,0.4

## LC 2020 (5050 metric) [mm]
height 4.5
pads (4):
  rrect15% 1.3x1.7 smd paste-0.015 mask+0.05: 1(-1.1,1.5) 2(1.1,1.5) 3(1.1,-1.5) 4(-1.1,-1.5)
Top Overlay:
  lines w0.15: -2.5,-2.5 -2.5,2.5 2.5,2.5 2.5,-2.5 -2.5,-2.5
Mechanical 13:
  lines w0.01: -2.5,-2.5 -2.5,2.5 2.5,2.5 2.5,-2.5 -2.5,-2.5
Mechanical 15:
  circle w0.1: c0,0 r0.05
  lines w0.1: -2.5,-2.5 -2.5,2.5 2.5,2.5 2.5,-2.5 -2.5,-2.5
3D body: height 0.45, standoff 0.01, extent -1.65,-2.25 -0.55,-0.75
3D body: height 0.45, standoff 0.01, extent 0.55,-2.25 1.65,-0.75
3D body: height 0.45, standoff 0.01, extent 0.55,0.75 1.65,2.25
3D body: height 0.45, standoff 0.01, extent -1.65,0.75 -0.55,2.25
3D body: height 4.5, standoff 0.45, extent -2.5,-2.5 2.5,2.5

## microSD Socket [mil]
height 73
pads (12):
  rrect15% 32x60 smd: 1(-305,433) 2(-262,417) 3(-219,433) 4(-176,441) 5(-133,433) 6(-90,441) 7(-47,433) 8(-4,433)
  rrect15% 72x56 smd: 9(-36,28)
  rrect15% 76x56 smd: 10(-261,28)
  rrect15% 56x76 smd: 11(-490,585) 12(28,546)
Top Overlay:
  lines w7.87: -500,522.64 -500,28 -499,27 -460,27 -460,16 ; -459,14 -323.82,14 ; -437.99,606 -417,606 -360,549 -360,548 -21,548 -18.26,550.74 ; -202.76,13.78 -92.52,13.78 ; 23.62,14 47,14 47,486.22
3D body "Tyco_microSD_c-1827034-01-b-3d.stp": height 74.05, standoff 0, extent -501.97,15.75 51.18,614.17

## RJLD-260TC1 [mm] "RJ45 Ethernet connector by TAIMAG"
height 14.89
pads (16):
  rrect50% 1.7x1.7 hole 1.05: 1(-4.445,3.3)
  round 1.7 hole 1.05: 2(-3.175,5.84) 3(-1.905,3.3) 4(-0.635,5.84) 5(0.635,3.3) 6(1.905,5.84) 7(3.175,3.3) 8(4.445,5.84)
  round 2 hole 1.05: 9(-6.35,-7.95) 10(-3.81,-6.43) 11(3.81,-7.95) 12(6.35,-6.43)
  round 3.4 hole 2: 13(-7.79,0) 14(7.79,0)
  round 2.95 hole 3.2 unplated: MH3(-5.715,-3.05) MH4(5.715,-3.05)
Top Overlay:
  lines w0.2: -7.885,-2.05 -7.885,-9.296 7.885,-9.296 7.885,-2.05 ; -7.885,2 -7.885,7.71 7.885,7.71 7.885,1.975 ; -4.944,-7.839 -4.944,-8.347 -4.055,-8.347 ; -3.013,-8.855 -3.013,-7.864 ; -3.013,-8.347 -2.429,-8.347 -2.429,-7.839 ; 2.769,-7.01 2.438,-6.68 2.438,-6.094 3.023,-6.094 ; 3.023,-6.577 3.023,-5.586 ; 4.064,-6.094 4.953,-6.094 4.953,-5.664 5.105,-5.512 5.41,-5.512 ; -4.055,-8.855 -4.055,-7.864 -3.064,-8.347 -4.055,-8.855 ; 3.073,-6.094 4.064,-6.577 4.064,-5.586 3.073,-6.094
  text "Y" at 1.372,-6.096 h1.52
  text "G" at -2.21,-6.071 h1.52
3D body "c-5-6605301-1-c-3d.stp": height 14.57, standoff -4.22, extent -8.879,-14.283 9.021,6.723

## USB2.0-4H4 3D FOX [mm] "Connector; USB1.1, Type A, Thru-Hole; 4 Position; Right Angle"
height 13.83
pads (8):
  rrect50% 1.6x1.9 hole 1.1: 1(-6,0)
  oval 1.6x1.9 hole 1.1: 2(-4,0) 3(-2,0) 4(0,0)
  round 2.5 hole 1.7: 5(-6.73,2.72) 5(0.27,2.72) 6(-6.73,-2.72) 6(0.27,-2.72)
Top Overlay:
  circle w0.25: c-7.212,-1.194 r0.125
  lines w0.2: -5.225,-2.896 -1.259,-2.896 ; -5.225,2.864 -1.259,2.864
3D body: height 2, standoff 0, extent -7.375,-2.975 -6.025,-2.575
3D body: height 2, standoff 0, extent -7.375,2.575 -6.025,2.975
3D body: height 2, standoff 0, extent -0.499,2.575 0.851,2.975
3D body: height 2, standoff 0, extent -0.499,-2.975 0.851,-2.575
3D body "Tyco_USBA_tipoFox_c-0292336-01-a-3d.stp": height 14.55, standoff -3.56, extent -18.518,-3.6 1.142,3.524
